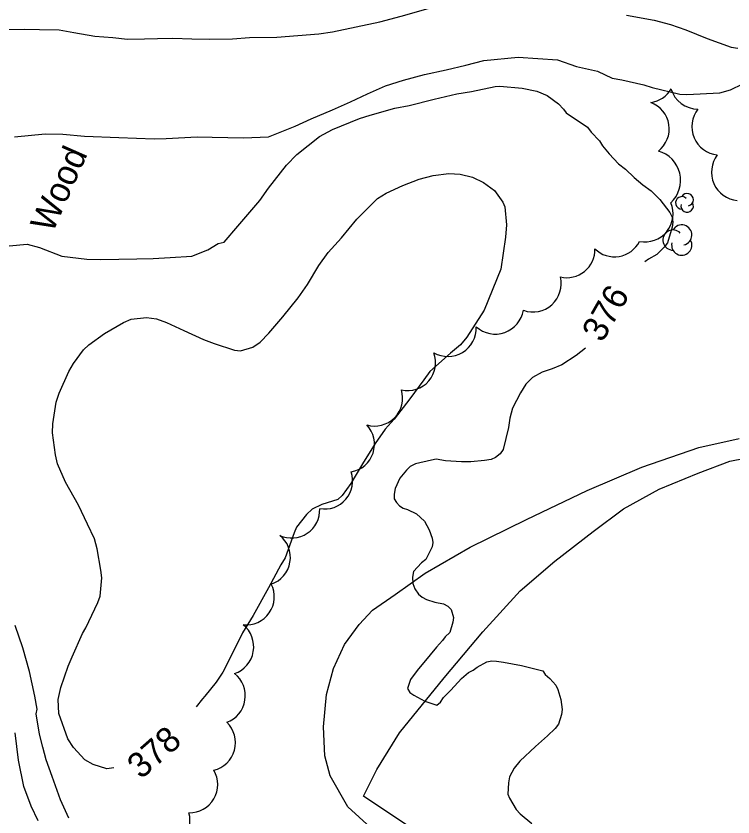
# Model space of a CAD drawing. Extents: x 287698 to 290158, y 5234163 to 5237182.
# Drawn here: x 288870.6 to 288956.3, y 5235117.7 to 5235213.3 of the extents above; entities that cross this region are included whole.
import ezdxf

# ---------------------------------------------------------------- set-up
doc = ezdxf.new("R2010")
doc.units = 0
for name, color, linetype in [('Niveau 2', 7, 'Continuous'), ('Niveau 22', 7, 'Continuous'), ('Niveau 44', 7, 'Continuous'), ('Niveau 56', 7, 'Continuous')]:
    doc.layers.add(name, color=color, linetype=linetype)

msp = doc.modelspace()

# ---------------------------------------------------------------- linework, layer by layer
at = {"layer": 'Niveau 2'}
for points in [[(288869.42, 5235211.69), (288871.58, 5235211.73), (288873.43, 5235211.67), (288875.79, 5235211.62), (288877.54, 5235211.34), (288880.02, 5235210.87), (288882.18, 5235210.71), (288883.92, 5235210.53), (288885.97, 5235210.57), (288887.51, 5235210.6), (288889.36, 5235210.64), (288891.62, 5235210.58), (288893.68, 5235210.52), (288896.46, 5235210.57), (288898.5, 5235210.71), (288901.79, 5235210.77), (288906.79, 5235211.17), (288908.44, 5235211.41), (288911.24, 5235212), (288914.09, 5235212.61), (288916.63, 5235213.28), (288919.87, 5235214.2)], [(288943.56, 5235213.39), (288946.85, 5235212.81), (288948.8, 5235212.29), (288950.62, 5235211.62), (288953.18, 5235210.6), (288956.04, 5235209.58), (288956.84, 5235209.46)], [(288870.45, 5235198.87), (288874.11, 5235199.21), (288876.21, 5235199.18), (288878.8, 5235198.94), (288882.91, 5235198.8), (288887.12, 5235198.61), (288888.57, 5235198.67), (288892.24, 5235198.85), (288894.04, 5235198.81), (288897.79, 5235198.76), (288900.78, 5235198.87), (288903.95, 5235200.15), (288905.88, 5235201.01), (288908.43, 5235202.08), (288910.56, 5235203.05), (288912.6, 5235204.01), (288914.74, 5235204.97), (288916.89, 5235205.63), (288919.43, 5235206.29), (288921.99, 5235206.85), (288924.34, 5235207.42), (288926.49, 5235207.97), (288930.59, 5235208.38), (288935.32, 5235208.06), (288937.59, 5235207.28), (288940.07, 5235206.72), (288941.84, 5235205.88), (288942.98, 5235205.65), (288945.62, 5235205.09), (288946.62, 5235204.74), (288949.91, 5235203.94), (288950.75, 5235203.9), (288954.71, 5235204.12), (288955.95, 5235204.46), (288957.46, 5235205.19)], [(288869.81, 5235185.86), (288871.95, 5235186.05), (288873.42, 5235185.64), (288876.08, 5235184.61), (288879.09, 5235184.28), (288880.73, 5235184.21), (288882.89, 5235184.25), (288885.05, 5235184.3), (288887, 5235184.33), (288889.05, 5235184.47), (288891.61, 5235184.63), (288893.55, 5235185.38), (288894.77, 5235186.12), (288895.5, 5235186.29), (288897.13, 5235188.19), (288899.74, 5235191.27), (288900.77, 5235192.73), (288902.93, 5235195.49), (288904.18, 5235196.76), (288906.86, 5235198.89), (288908.43, 5235199.75), (288911.64, 5235201.05), (288912.92, 5235201.46), (288915.88, 5235202.27), (288917.58, 5235202.62), (288920.58, 5235203.35), (288923.27, 5235204), (288925.01, 5235204.29), (288927.86, 5235204.89), (288928.42, 5235204.92), (288931.07, 5235204.69), (288932.83, 5235204.31), (288934.05, 5235203.78), (288935.41, 5235202.82), (288936.02, 5235202.18), (288936.34, 5235201.72)], [(288936.34, 5235201.72), (288938.88, 5235200), (288939.33, 5235199.43), (288940.3, 5235198.39), (288940.68, 5235197.81), (288941.47, 5235196.84), (288942.6, 5235195.65), (288943.42, 5235195.01), (288944.46, 5235194.02), (288945.51, 5235193.14), (288946.51, 5235192.4), (288947.51, 5235191.37), (288948.74, 5235189.83), (288949.01, 5235189.26), (288949.09, 5235188.69), (288949, 5235188.08), (288948.45, 5235186.21), (288948.03, 5235185.69), (288947.15, 5235184.83), (288946.17, 5235184.25), (288945.72, 5235183.94)], [(288882.29, 5235123.53), (288881.48, 5235123.41), (288879.85, 5235123.93), (288878.85, 5235124.5), (288877.47, 5235125.95), (288876.81, 5235127.01), (288875.72, 5235130.03), (288875.65, 5235131.68), (288875.98, 5235133.12), (288876.83, 5235135.68), (288877.32, 5235136.79), (288878.56, 5235139.56), (288878.95, 5235140.24), (288880.38, 5235143.28), (288880.66, 5235144.05), (288880.88, 5235146.2), (288880.76, 5235147.15), (288880.31, 5235149.68), (288879.99, 5235150.89), (288879.16, 5235152.63), (288878.07, 5235154.89), (288876.54, 5235157.65), (288875.58, 5235159.83), (288875.32, 5235160.92), (288874.97, 5235163.52), (288875.01, 5235164.6), (288875.42, 5235167.19), (288875.78, 5235168.25), (288876.93, 5235170.86), (288877.48, 5235171.81), (288878.67, 5235173.43), (288879.31, 5235174.04), (288881.18, 5235175.37), (288883.44, 5235176.69), (288884.38, 5235177.08), (288886.22, 5235177.3), (288887.41, 5235177.14), (288888.6, 5235176.71), (288890.66, 5235175.75), (288893.03, 5235174.66), (288894.27, 5235174.2), (288896.71, 5235173.41), (288897.43, 5235173.32), (288898.91, 5235173.76), (288899.8, 5235174.36), (288900.82, 5235175.41), (288902.48, 5235177.38), (288904.32, 5235179.64), (288905.42, 5235181.25), (288906.78, 5235183.52), (288907.91, 5235185.06), (288909.48, 5235186.81), (288911.34, 5235189.03), (288913.81, 5235191.49), (288914.84, 5235192.13), (288916.84, 5235193.07), (288918.78, 5235193.81), (288920.43, 5235194.24), (288922.34, 5235194.47), (288923.66, 5235194.41), (288925.16, 5235194.05), (288926.47, 5235193.41), (288927.76, 5235192.45), (288928.79, 5235191.08), (288929, 5235190.52), (288929.21, 5235188.36), (288929.1, 5235186.88), (288928.53, 5235183.08)], [(288928.53, 5235183.08), (288926.55, 5235178.19), (288924.46, 5235174.94), (288923.72, 5235174.04), (288922.51, 5235173.04), (288920.04, 5235170.85), (288919.34, 5235169.87), (288917.67, 5235167.57), (288915.8, 5235165.18), (288914.71, 5235163.97), (288913.53, 5235162.25), (288912.01, 5235159.84), (288910.63, 5235157.5), (288909.59, 5235156.04), (288909.06, 5235155.58), (288907.15, 5235154.99), (288906, 5235154.4), (288905.3, 5235153.79), (288904.14, 5235152.27), (288903.85, 5235151.61), (288902.78, 5235148.62), (288902.27, 5235147.76), (288900.76, 5235145.01), (288898.93, 5235141.71), (288897.69, 5235139.65), (288896.65, 5235137.56), (288895.34, 5235134.95), (288894.52, 5235133.75), (288893.16, 5235132.08), (288892.89, 5235131.76)], [(288938.63, 5235173.63), (288937.55, 5235172.78), (288935.81, 5235171.64), (288934.68, 5235171.15), (288933.46, 5235170.76), (288932.31, 5235170.14), (288931.5, 5235169.33), (288930.87, 5235168.31), (288929.94, 5235166.48), (288929.62, 5235165.26), (288929.43, 5235164.15), (288928.8, 5235161.52), (288928.45, 5235161.02), (288927.88, 5235160.57), (288927.38, 5235160.35), (288926.6, 5235160.21), (288924.95, 5235160.07), (288923.83, 5235160.06), (288921.93, 5235160.2), (288920.82, 5235160.37), (288920.26, 5235160.27), (288918.35, 5235159.83), (288917.7, 5235159.5), (288917.28, 5235159.09), (288916.47, 5235158.13), (288915.92, 5235156.87), (288915.8, 5235156.2), (288915.81, 5235155.65), (288916.05, 5235155.2), (288916.43, 5235154.83), (288916.87, 5235154.55), (288917.37, 5235154.36), (288918.44, 5235153.87), (288919.42, 5235152.98), (288919.99, 5235151.95), (288920.34, 5235150.97), (288920.41, 5235150.43), (288920.32, 5235149.92), (288919.58, 5235148.39), (288919.06, 5235147.99), (288918.11, 5235146.96), (288918, 5235146.31), (288918.03, 5235145.55), (288918.26, 5235144.92), (288918.71, 5235144.25), (288919.12, 5235143.9), (288919.66, 5235143.64), (288920.65, 5235143.3), (288921.68, 5235143.1), (288922.2, 5235142.85), (288922.59, 5235142.43), (288922.89, 5235141.47), (288922.8, 5235140.93), (288922.43, 5235139.68), (288921.88, 5235139.17), (288921.58, 5235138.73), (288920.84, 5235137.93), (288920.1, 5235137.02), (288918.53, 5235135.15), (288917.73, 5235134.09), (288917.38, 5235133.01), (288917.68, 5235132.53), (288918.15, 5235132.23), (288919.45, 5235131.51), (288920.88, 5235131.01), (288921.33, 5235131.36), (288921.7, 5235131.93), (288922.56, 5235132.79), (288923.84, 5235134.19), (288924.66, 5235134.92), (288925.24, 5235135.2), (288925.71, 5235135.57)], [(288876.92, 5235117.52), (288875.94, 5235119.73), (288874.94, 5235122.52), (288874.2, 5235124.5), (288873.82, 5235126.01), (288873.44, 5235127.54), (288873.04, 5235129.99), (288873.13, 5235130.53), (288872.86, 5235132.11), (288872.22, 5235135.02), (288871.42, 5235137.86), (288870.53, 5235140.52)], [(288925.71, 5235135.57), (288926.88, 5235136.19), (288927.45, 5235136.32), (288928.03, 5235136.29), (288928.84, 5235136.15), (288931, 5235135.77)], [(288931, 5235135.77), (288933.55, 5235135.12), (288933.83, 5235134.66), (288934.38, 5235134.2), (288935.12, 5235133.42), (288935.35, 5235132.89), (288935.69, 5235131.71), (288935.84, 5235130.51), (288935.76, 5235129.92), (288935.41, 5235128.76), (288935.01, 5235128.22), (288934.11, 5235127.36), (288932.69, 5235126.09), (288930.8, 5235124.35), (288930.12, 5235123.5), (288929.57, 5235122.46), (288929.43, 5235121.75), (288929.37, 5235120.4), (288929.57, 5235119.92), (288930.37, 5235118.58), (288930.86, 5235118.04), (288932.25, 5235116.91)], [(288892.89, 5235131.76), (288892.12, 5235130.83)], [(288873.28, 5235117.22), (288872.43, 5235118.95), (288871.57, 5235121.29), (288870.91, 5235124.44), (288870.5, 5235127.71)]]:
    msp.add_lwpolyline(points, dxfattribs=at)
at = {"layer": 'Niveau 22'}
msp.add_lwpolyline([(288914.76, 5235114.77), (288910.26, 5235118.89), (288908.15, 5235122.58), (288907.5, 5235124.97), (288907.33, 5235128.43), (288907.69, 5235132.3), (288908.56, 5235135.38), (288909.84, 5235138.28), (288911.6, 5235140.63), (288913.22, 5235142.34), (288915.93, 5235144.23), (288919.48, 5235146.76), (288924.85, 5235149.89), (288931.58, 5235153.19), (288938.83, 5235156.65), (288945.36, 5235159.45), (288952.2, 5235161.76), (288957.01, 5235162.84)], dxfattribs=at)
at = {"layer": 'Niveau 44'}
for centre, radius, start, end in [((288954.752, 5235200.08), 3.399, 141.83408, 263.87997), ((288957.091, 5235194.642), 3.396, 142.68931, 264.74613), ((288950.155, 5235190.99), 0.744, 44.11537, 269.80396), ((288950.795, 5235191.362), 0.744, 282.26917, 149.72626), ((288950.795, 5235190.618), 0.744, 166.93686, 29.62123), ((288949.107, 5235186.542), 1.208, 44.11537, 269.80396), ((288950.145, 5235187.146), 1.208, 282.26917, 149.72626), ((288950.145, 5235185.938), 1.208, 166.93686, 29.62123), ((288903.545, 5235154.328), 3.356, 244.87343, 2.52216), ((288898.119, 5235143.95), 3.351, 263.50858, 27.17471), ((288894.632, 5235132.142), 3.38, 290.21555, 51.8493), ((288893.434, 5235126.537), 3.394, 283.73774, 45.80279), ((288891.353, 5235121.527), 3.357, 268.75628, 30.6887), ((288888.022, 5235117.286), 3.376, 253.44186, 15.18421)]:
    msp.add_arc(centre, radius, start, end, dxfattribs=at)
for centre, major_axis, ratio, start_param, end_param in [((288945.954, 5235206.275), (2.467, -2.297), 0.98547, 5.603494, 6.51576), ((288952.077, 5235205.552), (1.596, -2.975), 0.994255, 4.510395, 5.789409), ((288945.296, 5235199.811), (3.313, 0.523), 0.999716, 5.214859, 7.346199), ((288946.379, 5235193.661), (3.616, -0.335), 0.999965, 5.54933, 7.675736), ((288945.731, 5235189.685), (0.29, 3.362), 0.999117, 3.039489, 5.195694), ((288942.102, 5235187.908), (3.084, -1.357), 0.997363, 4.357533, 6.223517), ((288936.411, 5235185.422), (-1.027, 3.21), 0.998594, 2.603428, 4.425038), ((288932.376, 5235181.333), (0.934, -3.242), 0.99937, 5.655848, 7.815178), ((288927.861, 5235178.734), (0.848, -3.313), 0.99949, 5.309867, 7.43496), ((288922.2, 5235176.048), (1.775, -2.906), 0.999044, 5.218028, 7.34187), ((288917.398, 5235171.921), (2.538, -2.186), 0.993734, 5.197647, 7.355273), ((288913.446, 5235167.695), (2.955, -1.597), 0.999844, 4.925356, 7.073121), ((288910.093, 5235162.163), (1.048, 3.173), 0.999984, 3.631175, 5.793603), ((288907.472, 5235157.798), (2.758, -1.925), 0.999882, 5.150961, 7.216955), ((288900.046, 5235148.66), (2.876, -1.717), 0.999959, 5.570798, 7.724439), ((288895.659, 5235137.985), (0.58, 3.307), 0.999984, 3.636509, 5.788269)]:
    msp.add_ellipse(centre, major_axis=major_axis, ratio=ratio, start_param=start_param, end_param=end_param, dxfattribs=at)
at = {"layer": 'Niveau 56'}
for points in [[(288912.12, 5235120.17), (288913.73, 5235123.32), (288916.42, 5235127.72), (288921.76, 5235134.29), (288926.39, 5235139.79), (288930.86, 5235144.65), (288935, 5235148.2), (288939.55, 5235151.77), (288943.19, 5235154.45), (288947.46, 5235156.79), (288952.12, 5235158.71), (288955.89, 5235160.14), (288961.17, 5235161.19)], [(288970.86, 5235080.91), (288912.12, 5235120.17)]]:
    msp.add_lwpolyline(points, dxfattribs=at)

# ---------------------------------------------------------------- texts
at = {"layer": 'Niveau 2'}
for s, rotation, p in [('376', 60.1914, (288940.65, 5235174.2)), ('378', 41.20222, (288885.55, 5235122.09))]:
    msp.add_text(s, height=3, rotation=rotation, dxfattribs=at).set_placement(p)
at = {"layer": 'Niveau 44'}
msp.add_text('Wood', height=3, rotation=66.12117, dxfattribs=at).set_placement((288874.97, 5235187.27))

doc.saveas('drawing.dxf')
